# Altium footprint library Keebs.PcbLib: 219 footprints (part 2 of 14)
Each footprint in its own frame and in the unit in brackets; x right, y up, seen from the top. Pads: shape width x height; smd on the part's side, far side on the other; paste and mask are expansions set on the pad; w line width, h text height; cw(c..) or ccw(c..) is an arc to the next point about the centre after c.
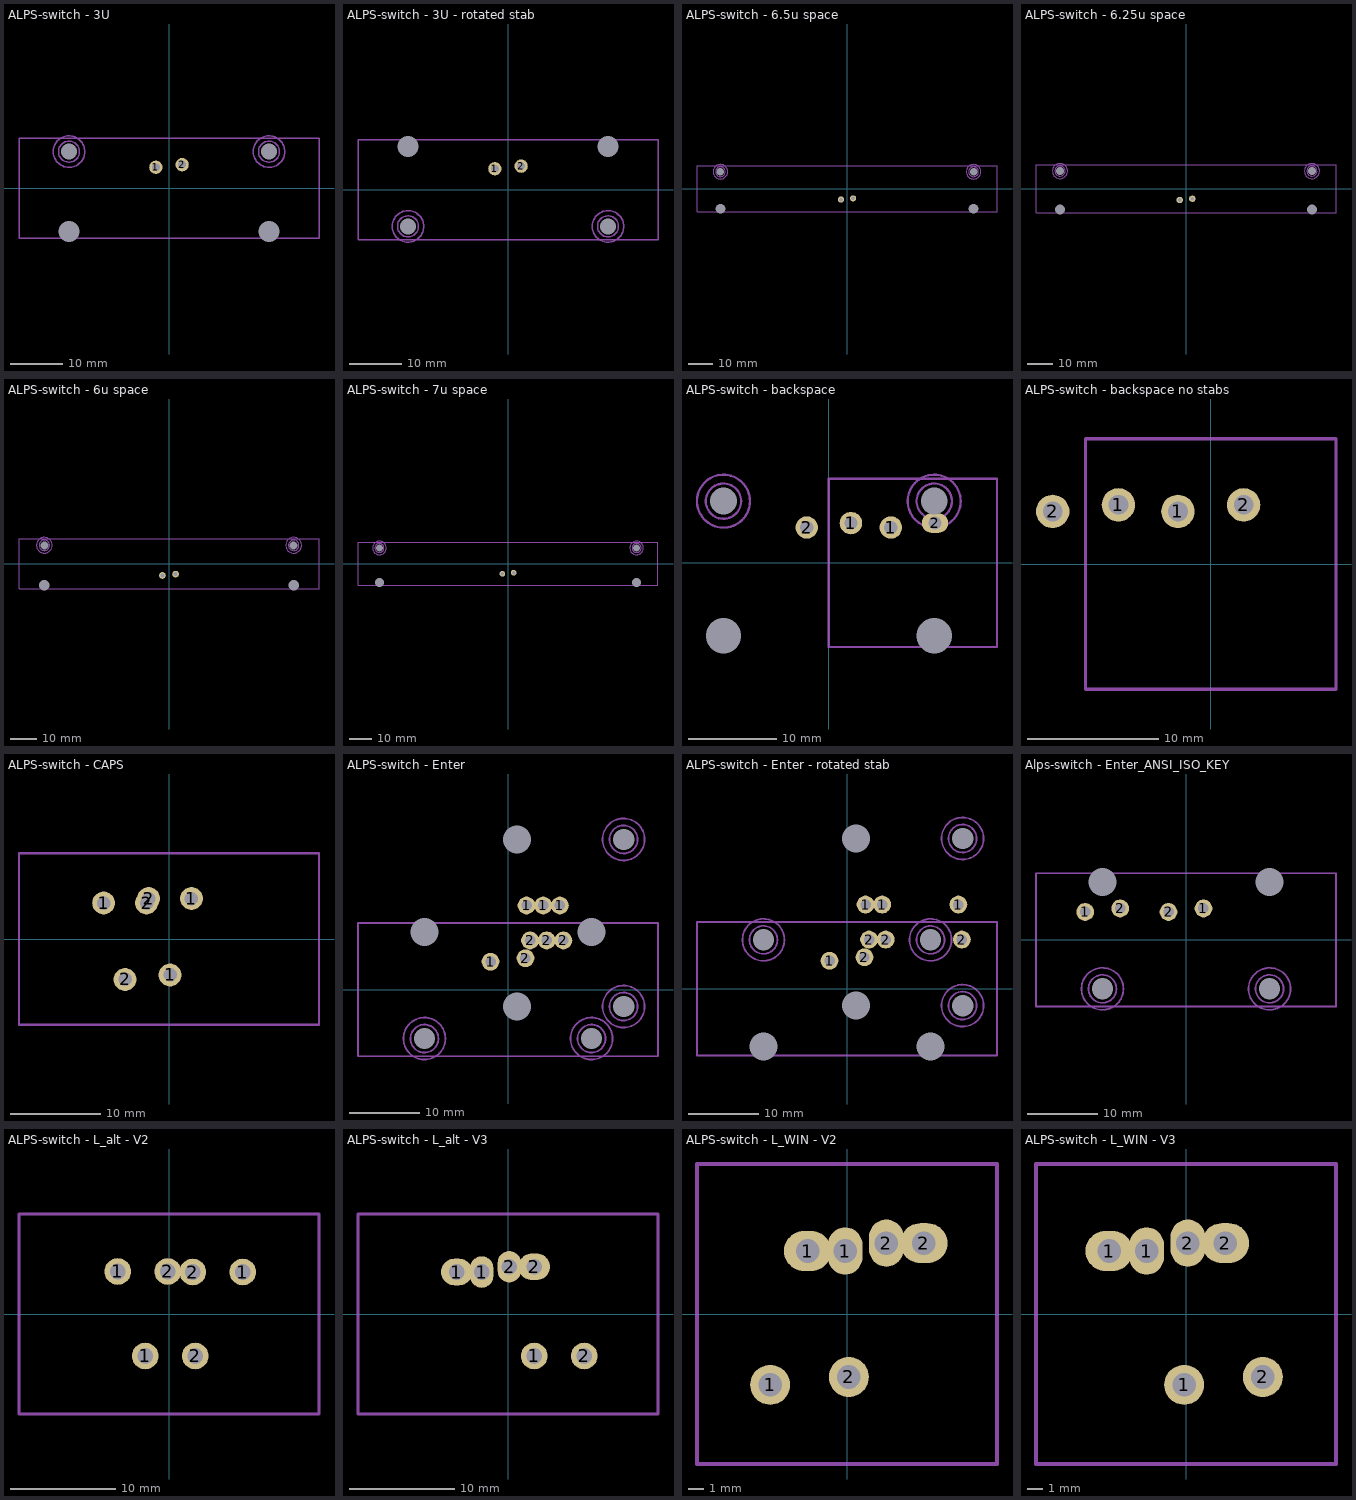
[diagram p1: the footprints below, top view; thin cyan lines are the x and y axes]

## ALPS-switch - 3U [mm]
pads (7):
  round 2.54 hole 1.5 mask-0.5: 1(-2.5,4) 2(2.5,4.5)
  round 1.524 hole 4 unplated: ""(-19.05,-8.255) ""(19.05,-8.255)
  round 1.524 hole 3.048 unplated: ""(-19.05,6.985) ""(19.05,6.985)
  round 1 on Mech13: ""(0,0)
Mechanical 13:
  lines w0.254: -28.575,-9.525 28.575,-9.525 28.575,9.525 -28.575,9.525 -28.575,-9.525
  text ".Designator" at -3.825,-3.375 h0.7
Mechanical 15:
  circle w0.254: c-19.05,6.985 r3
  circle w0.254: c-19.05,6.985 r2
  circle w0.254: c19.05,6.985 r3
  circle w0.254: c19.05,6.985 r2

## ALPS-switch - 3U - rotated stab [mm]
pads (7):
  round 2.54 hole 1.5 mask-0.5: 1(-2.5,4) 2(2.5,4.5)
  round 1.524 hole 3.048 unplated: ""(-19.05,-6.985) ""(19.05,-6.985)
  round 1.524 hole 4 unplated: ""(-19.05,8.255) ""(19.05,8.255)
  round 1 on Mech13: ""(0,0)
Mechanical 13:
  lines w0.254: -28.575,-9.525 28.575,-9.525 28.575,9.525 -28.575,9.525 -28.575,-9.525
  text ".Designator" at -3.825,-3.375 h0.7
Mechanical 15:
  circle w0.254: c19.05,-6.985 r3
  circle w0.254: c19.05,-6.985 r2
  circle w0.254: c-19.05,-6.985 r3
  circle w0.254: c-19.05,-6.985 r2

## ALPS-switch - 6.5u space [mm]
pads (7):
  round 2.54 hole 1.5 mask-0.5: 1(2.5,-4) 2(-2.5,-4.5)
  round 1.524 hole 4 unplated: ""(-52.25,-8.255) ""(52.25,-8.255)
  round 1.524 hole 3.048 unplated: ""(-52.25,6.985) ""(52.25,6.985)
  round 1 on Mech13: ""(0,0)
Mechanical 13:
  lines w0.254: -61.912,-9.525 -61.912,9.525 61.912,9.525 61.912,-9.525 -61.912,-9.525
  text ".Designator" at -3.575,-3.7 h0.7
Mechanical 15:
  circle w0.254: c-52.25,6.985 r3
  circle w0.254: c-52.25,6.985 r2
  circle w0.254: c52.25,6.985 r3
  circle w0.254: c52.25,6.985 r2

## ALPS-switch - 6.25u space [mm]
pads (7):
  round 2.54 hole 1.5 mask-0.5: 1(2.5,-4) 2(-2.5,-4.5)
  round 1.524 hole 4 unplated: ""(-50,-8.255) ""(50,-8.255)
  round 1.524 hole 3.048 unplated: ""(-50,6.985) ""(50,6.985)
  round 1 on Mech13: ""(0,0)
Mechanical 13:
  lines w0.254: -59.531,-9.525 -59.531,9.525 59.531,9.525 59.531,-9.525 -59.531,-9.525
  text ".Designator" at -3.575,-3.7 h0.7
Mechanical 15:
  circle w0.254: c50,6.985 r2
  circle w0.254: c50,6.985 r3
  circle w0.254: c-50,6.985 r2
  circle w0.254: c-50,6.985 r3

## ALPS-switch - 6u space [mm]
pads (7):
  round 2.54 hole 1.5 mask-0.5: 1(2.5,-4) 2(-2.5,-4.5)
  round 1.524 hole 4 unplated: ""(-47.5,-8.255) ""(47.5,-8.255)
  round 1.524 hole 3.048 unplated: ""(-47.5,6.985) ""(47.5,6.985)
  round 1 on Mech13: ""(0,0)
Mechanical 13:
  lines w0.254: -57.15,-9.525 57.15,-9.525 57.15,9.525 -57.15,9.525 -57.15,-9.525
  text ".Designator" at -3.575,-3.7 h0.7
Mechanical 15:
  circle w0.254: c-47.5,6.985 r3
  circle w0.254: c-47.5,6.985 r2
  circle w0.254: c47.5,6.985 r3
  circle w0.254: c47.5,6.985 r2

## ALPS-switch - 7u space [mm]
pads (7):
  round 2.54 hole 1.5 mask-0.5: 1(2.5,-4) 2(-2.5,-4.5)
  round 1.524 hole 4 unplated: ""(-57.15,-8.255) ""(57.15,-8.255)
  round 1.524 hole 3.048 unplated: ""(-57.15,6.985) ""(57.15,6.985)
  round 1 on Mech13: ""(0,0)
Mechanical 13:
  lines w0.254: -66.675,-9.525 -66.675,9.525 66.675,9.525 66.675,-9.525 -66.675,-9.525
  text ".Designator" at -3.575,-3.7 h0.7
Mechanical 15:
  circle w0.254: c57.15,6.985 r2
  circle w0.254: c57.15,6.985 r3
  circle w0.254: c-57.15,6.985 r2
  circle w0.254: c-57.15,6.985 r3

## ALPS-switch - backspace [mm]
pads (10):
  round 2.54 hole 1.5 mask-0.5: 1(2.5,4.5) 1(7.025,4) 2(-2.5,4)
  oval 3x2.2 hole 1.5 mask-0.7: 2(12.025,4.5)
  round 1.524 hole 4 unplated: ""(-11.938,-8.255) ""(11.938,-8.255)
  round 1.524 hole 3.048 unplated: ""(-11.938,6.985) ""(11.938,6.985)
  round 1 on Mech13: ""(0,0) ""(9.525,0)
Mechanical 13:
  lines w0.254: 0,-9.525 0,9.525 19.05,9.525 19.05,-9.525 0,-9.525
  text ".Designator" at 6.65,3.75 h0.7
Mechanical 15:
  circle w0.254: c-11.938,6.985 r3
  circle w0.254: c-11.938,6.985 r2
  circle w0.254: c11.938,6.985 r3
  circle w0.254: c11.938,6.985 r2

## ALPS-switch - backspace no stabs [mm]
pads (6):
  round 2.54 hole 1.5 mask-0.5: 1(-7.025,4.5) 1(-2.5,4) 2(-12.025,4) 2(2.5,4.5)
  round 1 on Mech13: ""(-9.525,0) ""(0,0)
Mechanical 13:
  lines w0.254: -9.525,-9.525 9.525,-9.525 9.525,9.525 -9.525,9.525 -9.525,-9.525
  text ".Designator" at -2.875,3.75 h0.7

## ALPS-switch - CAPS [mm] "Footprint supports both common versions of stepped capslock"
pads (9):
  round 2.54 hole 1.5 mask-0.5: 1(-7.263,4) 1(0.119,-4) 1(2.5,4.5) 2(-4.881,-4.5) 2(-2.5,4) 2(-2.262,4.5)
  round 1 on Mech13: ""(-4.763,0) ""(-2.381,0) ""(0,0)
Mechanical 13:
  lines w0.254: -16.669,-9.525 16.669,-9.525 ; -16.669,-9.525 16.669,-9.525 ; -16.669,-9.525 -16.669,9.525 16.669,9.525 16.669,-9.525
  text ".Designator" at -7.85,-7.5 h0.7

## ALPS-switch - Enter [mm]
pads (20):
  round 2.54 hole 1.5 mask-0.5: 1(-2.5,4) 1(2.649,12.03) 1(5.03,12.03) 1(7.411,12.03) 2(2.5,4.5) 2(3.149,7.03) 2(5.53,7.03) 2(7.911,7.03)
  round 1.524 hole 3.048 unplated: ""(-11.938,-6.985) ""(11.938,-6.985) ""(16.515,-2.408) ""(16.515,21.468)
  round 1.524 hole 4 unplated: ""(-11.938,8.255) ""(1.275,-2.408) ""(1.275,21.468) ""(11.938,8.255)
  round 1 on Mech13: ""(0,0) ""(7.149,9.53) ""(9.53,9.53) ""(11.911,9.53)
Mechanical 13:
  lines w0.254: -21.431,-9.525 -21.431,9.525 21.431,9.525 21.431,-9.525 -21.431,-9.525
  text ".Designator" at 7.85,1.8 h0.7
Mechanical 15:
  circle w0.254: c16.515,21.468 r2
  circle w0.254: c16.515,21.468 r3
  circle w0.254: c16.515,-2.408 r2
  circle w0.254: c16.515,-2.408 r3
  circle w0.254: c11.938,-6.985 r2
  circle w0.254: c11.938,-6.985 r3
  circle w0.254: c-11.938,-6.985 r2
  circle w0.254: c-11.938,-6.985 r3

## ALPS-switch - Enter - rotated stab [mm]
pads (20):
  round 2.54 hole 1.5 mask-0.5: 1(-2.5,4) 1(2.649,12.03) 1(5.03,12.03) 1(15.911,12.03) 2(2.5,4.5) 2(3.149,7.03) 2(5.53,7.03) 2(16.411,7.03)
  round 1.524 hole 4 unplated: ""(-11.938,-8.255) ""(1.275,-2.408) ""(1.275,21.468) ""(11.938,-8.255)
  round 1.524 hole 3.048 unplated: ""(-11.938,6.985) ""(11.938,6.985) ""(16.515,-2.408) ""(16.515,21.468)
  round 1 on Mech13: ""(0,0) ""(7.149,9.53) ""(9.53,9.53) ""(11.911,9.53)
Mechanical 13:
  lines w0.254: -21.431,-9.525 -21.431,9.525 21.431,9.525 21.431,-9.525 -21.431,-9.525
  text ".Designator" at 7.85,1.8 h0.7
Mechanical 15:
  circle w0.254: c11.938,6.985 r2
  circle w0.254: c11.938,6.985 r3
  circle w0.254: c16.515,-2.408 r2
  circle w0.254: c16.515,-2.408 r3
  circle w0.254: c16.515,21.468 r2
  circle w0.254: c16.515,21.468 r3
  circle w0.254: c-11.938,6.985 r2
  circle w0.254: c-11.938,6.985 r3

## Alps-switch - Enter_ANSI_ISO_KEY [mm]
pads (12):
  round 2.54 hole 1.5 mask-0.5: 1(-14.406,4) 1(2.5,4.5) 2(-9.406,4.5) 2(-2.5,4)
  round 1.524 hole 3.048 unplated: ""(-11.938,-6.985) ""(11.938,-6.985)
  round 1.524 hole 4 unplated: ""(-11.938,8.255) ""(11.938,8.255)
  round 1 on Mech13: ""(-11.906,0) ""(-11.906,0) ""(0,0) ""(0,0)
Mechanical 13:
  lines w0.254: -21.431,-9.525 21.431,-9.525 21.431,9.525 -21.431,9.525 -21.431,-9.525
  text ".Designator" at 7.85,1.8 h0.7
Mechanical 15:
  circle w0.254: c11.938,-6.985 r2
  circle w0.254: c11.938,-6.985 r3
  circle w0.254: c-11.938,-6.985 r2
  circle w0.254: c-11.938,-6.985 r3

## ALPS-switch - L_alt - V2 [mm]
pads (9):
  round 2.54 hole 1.5 mask-0.5: 1(-4.881,4.048) 1(-2.262,-4) 1(7.025,4) 2(-0.119,4.048) 2(2.262,4) 2(2.5,-4)
  round 1 on Mech13: ""(-2.381,0.048) ""(0,0) ""(4.763,0)
Mechanical 13:
  lines w0.254: -14.287,-9.525 14.287,-9.525 14.287,9.525 -14.287,9.525 -14.287,-9.525
  text ".Designator" at -10.775,-6.175 h0.7

## ALPS-switch - L_alt - V3 [mm]
pads (9):
  oval 3x2.54 hole 1.5 mask-0.7: 1(-4.881,4) 2(2.5,4.5)
  oval 2.2x3 hole 1.5 mask-0.7: 1(-2.5,4) 2(0.119,4.5)
  round 2.54 hole 1.5 mask-0.5: 1(2.5,-4) 2(7.263,-4)
  round 1 on Mech13: ""(-2.381,0.048) ""(0,0) ""(4.763,0)
Mechanical 13:
  lines w0.254: -14.287,-9.525 -14.287,9.525 14.287,9.525 14.287,-9.525 -14.287,-9.525
  text ".Designator" at -10.775,-6.175 h0.7

## ALPS-switch - L_WIN - V2 [mm]
pads (9):
  round 2.54 hole 1.5 mask-0.5: 1(-4.881,-4.5) 2(0.119,-4)
  oval 3x2.54 hole 1.5 mask-0.7: 1(-2.5,4) 2(4.881,4.5)
  oval 2.2x3 hole 1.5 mask-0.7: 1(-0.119,4) 2(2.5,4.5)
  round 1 on Mech13: ""(-2.381,0) ""(0,0) ""(2.381,0)
Mechanical 13:
  lines w0.254: -9.525,-9.525 9.525,-9.525 9.525,9.525 -9.525,9.525 -9.525,-9.525
  text ".Designator" at -4.225,-8.325 h0.7

## ALPS-switch - L_WIN - V3 [mm]
pads (9):
  oval 3x2.54 hole 1.5 mask-0.7: 1(-4.881,4) 2(2.5,4.5)
  oval 2.2x3 hole 1.5 mask-0.7: 1(-2.5,4) 2(0.119,4.5)
  round 2.54 hole 1.5 mask-0.5: 1(-0.119,-4.5) 2(4.881,-4)
  round 1 on Mech13: ""(-2.381,0) ""(0,0) ""(2.381,0)
Mechanical 13:
  lines w0.254: -9.525,-9.525 9.525,-9.525 9.525,9.525 -9.525,9.525 -9.525,-9.525
  text ".Designator" at -4.225,-8.325 h0.7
